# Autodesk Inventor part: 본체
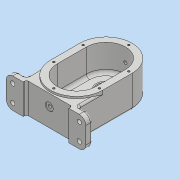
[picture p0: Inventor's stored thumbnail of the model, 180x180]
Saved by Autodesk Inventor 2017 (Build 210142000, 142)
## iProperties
Part Number: 본체
Material: 일반
Document SubType Name: Modeling
Designer: MRC
Density: 1 g/cm^3
Appearance: 기본값
Author: MRC
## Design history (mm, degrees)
sketch "스케치1"
  geometry: L1 (0, 0)-(0, -87); L2 (-40, 0)-(-40, -82); L3 (40, -82)-(40, 0); L4 (-40, -82)-(-61, -82); L5 (-61, -82)-(-61, -92); L6 (-61, -92)-(-35, -92); L7 (-35, -92)-(-35, -87); L8 (-35, -87)-(35, -87); L9 (35, -87)-(35, -92); L10 (35, -92)-(61, -92); L11 (61, -92)-(61, -82); L12 (61, -82)-(40, -82); A1 r 40 centre (0, 0) between (40, 0) and (-40, 0); 1 further point
  constraints: 26 end point, 5 perpendicular, 3 horizontal, 2 midpoint, 2 parallel, 2 point on circle, 2 point on line, 2 tangent, 2 vertical, 1 centre point
  dimensions: "d0" = 40 radius of A1; "d1" = 10 distance of L10.end L11.end; "d2" = 92 distance from line of L10 L1.start; "d3" = 5 distance of L8.end L9.end; "d4" = 70 distance of L7.end L8.end; "d5" = 122 distance between parallel lines of L11 L5; "d6" = 61 distance from line of point (0, -43.5) L5
extrude "돌출1" new body sketch "스케치1" distance "d7" = 46; taper "d8" = 0 deg
sketch "스케치2"
  geometry: L1 (0, 0)-(0, -45); L2 (-40, 0)-(-40, -45); L3 (40, -45)-(40, 0); A1 r 40 centre (0, 0) between (40, 0) and (-40, 0); A2 r 40 centre (0, -45) between (-40, -45) and (40, -45); A3 r 40 centre (0, 0) between (40, 0) and (-40, 0) reference; 1 further point
  constraints: 8 end point, 4 point on circle, 4 tangent, 2 centre point, 1 concentric, 1 midpoint, 1 parallel, 1 vertical
  dimensions: "d9" = 45 distance of L1.start L1.end
extrude "돌출2" join sketch "스케치2" distance "d10" = 3; taper "d11" = 0 deg
sketch "스케치3"
  geometry: L1 (0, 0)-(0, -45); L2 (-26, 0)-(-26, -45); L3 (26, -45)-(26, 0); A1 r 26 centre (0, 0) between (26, 0) and (-26, 0); A2 r 26 centre (0, -45) between (-26, -45) and (26, -45); 1 further point
  constraints: 8 end point, 4 point on circle, 4 tangent, 2 centre point, 1 midpoint, 1 parallel, 1 vertical
  dimensions: "d12" = 26 radius of A1; "d13" = 45 distance of L1.start L1.end
extrude "돌출3" join sketch "스케치3" distance "d14" = 11; taper "d15" = 0 deg
sketch "스케치4"
  geometry: L1 (-26, -45)-(-26, 0) reference; L2 (-26, -30)-(26, -30); L3 (26, 0)-(26, -45) reference; L4 (-26, 0)-(-26, -45) reference; L5 (26, -45)-(26, 0) reference; L6 (-26, -30)-(-26, 0); L7 (26, -30)-(26, 0); A1 r 26 centre (0, -45) between (-26, -45) and (26, -45) reference; A2 r 26 centre (0, 0) between (26, 0) and (-26, 0) reference; A3 r 26 centre (0, 0) between (26, 0) and (-26, 0); 1 further point
  constraints: 6 end point, 2 point on circle, 2 point on line, 1 centre point, 1 coincident, 1 collinear, 1 horizontal, 1 vertical
  dimensions: "d16" = 30 distance from line of L2 point (0, 0)
extrude "돌출4" cut sketch "스케치4" distance "d17" = 3; taper "d18" = 0 deg
sketch "스케치5"
  geometry: L1 (0, 0)-(0, -45); L2 (-30, 0)-(-30, -45); L3 (30, -45)-(30, 0); A1 r 30 centre (0, 0) between (30, 0) and (-30, 0); A2 r 30 centre (0, -45) between (-30, -45) and (30, -45); 1 further point
  constraints: 8 end point, 4 point on circle, 4 tangent, 2 centre point, 1 midpoint, 1 parallel, 1 vertical
  dimensions: "d19" = 45 distance of L1.start L1.end; "d20" = 30 radius of A1
extrude "돌출5" cut sketch "스케치5" distance "d21" = 41; taper "d22" = 0 deg
hole "구멍1" diameter "d25" = 20; stored, may be unused: countersink angle "d29" = 90 deg, drill point angle "d31" = 0 deg; dims "d23" = 10, "d24" = 10, "d26" = 6, "d27" = 28, "d28" = 8, "d30" = 12
hole "구멍2" diameter "d34" = 22; stored, may be unused: countersink angle "d38" = 90 deg, drill point angle "d40" = 0 deg; dims "d32" = 10, "d33" = 10, "d35" = 6, "d36" = 28, "d37" = 8, "d39" = 100
sketch "스케치6"
  geometry: C1 r 14 at (0, 0); 1 further point
  constraints: 1 centre point, 1 coincident
  dimensions: "d41" = 28 diameter of C1
extrude "돌출6" cut sketch "스케치6" distance "d42" = 4; taper "d43" = 0 deg
fillet "모깎기1" dims "d44" = 10
sketch "스케치7"
  geometry: L1 (-21, 36)-(-21, 10) reference; L2 (0, 0)-(-11, 0) reference; L3 (0, 46)-(0, 0) reference; L4 (0, 46)-(-11, 46) reference; L5 (91, 46)-(80, 46) reference; L6 (80, 46)-(80, 0) reference; L7 (91, 0)-(80, 0) reference; L8 (101, 36)-(101, 10) reference; A1 r 10 centre (-11, 36) between (-11, 46) and (-21, 36) reference; A2 r 10 centre (-11, 10) between (-21, 10) and (-11, 0) reference; A3 r 10 centre (91, 36) between (101, 36) and (91, 46) reference; A4 r 10 centre (91, 10) between (91, 0) and (101, 10) reference; 1 further point
hole "구멍3" sketch "스케치7" at (-11, 36), (-11, 10), (91, 36), (91, 10) diameter "d45" = 6.6; stored, may be unused: countersink angle "d49" = 90 deg, drill point angle "d51" = 0 deg; dims "d46" = 6, "d47" = 11, "d48" = 2, "d50" = 10
sketch "스케치8"
  geometry: L1 (0, 0)-(0, -45); L2 (-35, 0)-(-35, -45); L3 (35, -45)-(35, 0); C1 r 10 at (0, -45) reference; A1 r 35 centre (0, 0) between (35, 0) and (-35, 0); A2 r 35 centre (0, -45) between (-35, -45) and (35, -45); 7 further points
  constraints: 8 end point, 6 point on circle, 4 coincident, 4 tangent, 2 centre point, 1 midpoint, 1 parallel, 1 vertical
  dimensions: "d52" = 70 diameter of A2
hole "구멍4" sketch "스케치8" at (0, 35), (-35, 0), (35, 0), (35, -45), (-35, -45), (0, -80) diameter "d53" = 3.242; stored, may be unused: countersink angle "d57" = 90 deg, drill point angle "d59" = 118 deg; dims "d54" = 8, "d55" = 11, "d56" = 2, "d58" = 10
sketch "스케치9"
  geometry: L1 (75, 49)-(-5, 49) reference; L2 (0, 0)-(70, 0) reference; 3 further points
  constraints: 1 midpoint, 1 vertical alignment
  dimensions: "d60" = 21 distance from line of point (35, 28) L1
hole "구멍5" sketch "스케치9" at (35, 28) diameter "d61" = 4.917; stored, may be unused: countersink angle "d65" = 90 deg, drill point angle "d67" = 0 deg; dims "d62" = 12, "d63" = 12, "d64" = 1, "d66" = 17.1
node "작업 평면1"
sketch "스케치10"
  geometry: L1 (5, 49)-(-75, 49) reference; C1 r 6 at (-35, 28); 1 further point
  constraints: 1 centre point, 1 vertical alignment
  dimensions: "d69" = 12 diameter of C1; "d70" = 21 distance from line of L1 C1.centre
extrude "돌출7" join sketch "스케치10" stored distance "d71" = 4; taper "d72" = 0 deg
hole "구멍6" diameter "d75" = 4.917; stored, may be unused: countersink angle "d79" = 90 deg, drill point angle "d81" = 0 deg; dims "d73" = 10, "d74" = 10, "d76" = 20, "d77" = 12, "d78" = 1, "d80" = 20
chamfer "모따기1" distance "d82" = 1; stored, may be unused: second distance "d83" = 2, angle "d84" = 45 deg
fillet "모깎기2" dims "d85" = 5
fillet "모깎기3" dims "d86" = 3
fillet "모깎기4" dims "d87" = 3
fillet "모깎기5" dims "d88" = 0.3
sketch "스케치11"
  geometry: 2 further points
  constraints: 1 vertical alignment
  dimensions: "d89" = 20 distance of point (0, 0) point (0, 20)
hole "구멍7" sketch "스케치11" at (0, 20) diameter "d90" = 3.242; stored, may be unused: countersink angle "d94" = 90 deg, drill point angle "d96" = 0 deg; dims "d91" = 8, "d92" = 12, "d93" = 1, "d95" = 10
sketch "스케치12"
  geometry: L1 (51, -92)-(35, -92) reference; L2 (-35, -92)-(-51, -92) reference; A1 r 29 centre (0, -45) between (-29, -45) and (29, -45) reference; 3 further points
  constraints: 1 point on circle, 1 vertical alignment, 1 other
  dimensions: "d102" = 12 distance from line of L2 point (0, -80)
feature "엠보싱1" sketch "스케치12" dims "d0" = 40, "d1" = 10, "d2" = 92, "d3" = 5, "d4" = 70, "d5" = 122, "d6" = 61, "d9" = 45, "d100" = 0.5, "d101" = 0
fillet "모깎기6" dims "d103" = 3
node "솔리드1"
pattern_circular "원형 패턴1" dims angle "d98" = 360 deg
node "투영된 루프1"
node "투영된 루프2"
node "투영된 루프3"
other parameters: "d68" = -135
